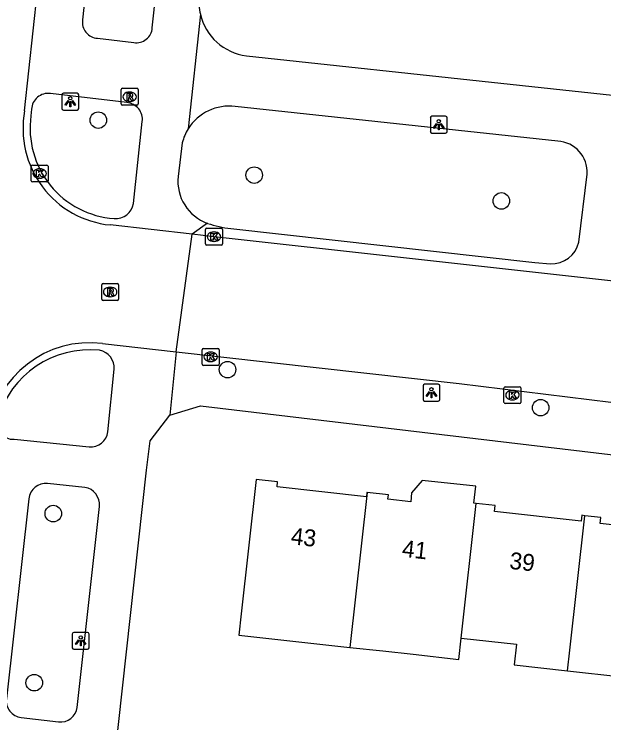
# Model space of a CAD drawing. Extents: x 162026 to 163499, y 387297 to 388169.
# Drawn here: x 162312.4 to 162347.33, y 387955.08 to 387997.02 of the extents above; entities that cross this region are included whole.
import ezdxf

# ---------------------------------------------------------------- set-up
doc = ezdxf.new("R2010")
doc.units = 0
for name, color, linetype in [('IMGEO_Boom', 7, 'Continuous'), ('IMGEO_Kolk', 7, 'Continuous'), ('IMGEO_Lichtpunt', 7, 'Continuous'), ('IMGEO_Pand', 7, 'Continuous'), ('IMGEO_Pand_nummerreeks', 7, 'Continuous'), ('IMGEO_Rijbaan_lokaal_gesloten', 7, 'Continuous'), ('IMGEO_Rijbaan_lokaal_open', 7, 'Continuous'), ('IMGEO_Rioolput', 7, 'Continuous'), ('IMGEO_Voetpad_open', 7, 'Continuous')]:
    doc.layers.add(name, color=color, linetype=linetype)

msp = doc.modelspace()

# ---------------------------------------------------------------- linework, layer by layer
at = {"layer": 'IMGEO_Boom'}
for centre in [(162317.382, 387990.753), (162326.617, 387987.499), (162341.256, 387985.971), (162325.039, 387975.985), (162343.583, 387973.734), (162314.714, 387967.468), (162313.588, 387957.457)]:
    msp.add_circle(centre, 0.489, dxfattribs=at)
at = {"layer": 'IMGEO_Kolk'}
for p, q in [((162313.403, 387987.169), (162313.403, 387988.021)), ((162313.478, 387988.095), (162314.33, 387988.095)), ((162314.404, 387988.021), (162314.404, 387987.169)), ((162313.891, 387987.875), (162313.916, 387987.875)), ((162314.33, 387987.095), (162313.478, 387987.095)), ((162313.914, 387987.315), (162313.889, 387987.315)), ((162323.732, 387983.428), (162323.732, 387984.28)), ((162323.807, 387984.354), (162324.659, 387984.354)), ((162324.733, 387984.28), (162324.733, 387983.428)), ((162324.22, 387984.134), (162324.245, 387984.134)), ((162324.659, 387983.354), (162323.807, 387983.354)), ((162324.243, 387983.574), (162324.218, 387983.574)), ((162323.534, 387976.315), (162323.534, 387977.167)), ((162323.609, 387977.241), (162324.461, 387977.241)), ((162324.022, 387977.021), (162324.047, 387977.021)), ((162324.535, 387977.167), (162324.535, 387976.315)), ((162324.461, 387976.241), (162323.609, 387976.241)), ((162324.045, 387976.461), (162324.02, 387976.461)), ((162341.487, 387974.975), (162342.339, 387974.975)), ((162341.412, 387974.049), (162341.412, 387974.901)), ((162341.9, 387974.755), (162341.925, 387974.755)), ((162342.413, 387974.901), (162342.413, 387974.049)), ((162341.923, 387974.195), (162341.898, 387974.195)), ((162342.339, 387973.975), (162341.487, 387973.975))]:
    msp.add_line(p, q, dxfattribs=at)
for points in [[(162313.403, 387987.169), (162313.403, 387988.021)], [(162313.478, 387988.095), (162314.33, 387988.095)], [(162314.404, 387988.021), (162314.404, 387987.169)], [(162313.724, 387987.795), (162313.847, 387987.795), (162313.847, 387987.644), (162313.977, 387987.795), (162314.141, 387987.795), (162313.995, 387987.644), (162314.148, 387987.395), (162313.996, 387987.395), (162313.911, 387987.559), (162313.847, 387987.492), (162313.847, 387987.395), (162313.724, 387987.395), (162313.724, 387987.795)], [(162314.33, 387987.095), (162313.478, 387987.095)], [(162323.732, 387983.428), (162323.732, 387984.28)], [(162323.807, 387984.354), (162324.659, 387984.354)], [(162324.733, 387984.28), (162324.733, 387983.428)], [(162324.053, 387984.054), (162324.176, 387984.054), (162324.176, 387983.903), (162324.306, 387984.054), (162324.47, 387984.054), (162324.324, 387983.903), (162324.477, 387983.654), (162324.325, 387983.654), (162324.24, 387983.818), (162324.176, 387983.751), (162324.176, 387983.654), (162324.053, 387983.654), (162324.053, 387984.054)], [(162324.659, 387983.354), (162323.807, 387983.354)], [(162323.534, 387976.315), (162323.534, 387977.167)], [(162323.609, 387977.241), (162324.461, 387977.241)], [(162324.535, 387977.167), (162324.535, 387976.315)], [(162323.855, 387976.941), (162323.978, 387976.941), (162323.978, 387976.79), (162324.108, 387976.941), (162324.272, 387976.941), (162324.126, 387976.79), (162324.279, 387976.541), (162324.127, 387976.541), (162324.042, 387976.705), (162323.978, 387976.638), (162323.978, 387976.541), (162323.855, 387976.541), (162323.855, 387976.941)], [(162324.461, 387976.241), (162323.609, 387976.241)], [(162341.487, 387974.975), (162342.339, 387974.975)], [(162341.412, 387974.049), (162341.412, 387974.901)], [(162341.733, 387974.675), (162341.856, 387974.675), (162341.856, 387974.524), (162341.986, 387974.675), (162342.15, 387974.675), (162342.004, 387974.524), (162342.157, 387974.275), (162342.005, 387974.275), (162341.92, 387974.439), (162341.856, 387974.372), (162341.856, 387974.275), (162341.733, 387974.275), (162341.733, 387974.675)], [(162342.413, 387974.901), (162342.413, 387974.049)], [(162342.339, 387973.975), (162341.487, 387973.975)]]:
    msp.add_lwpolyline(points, dxfattribs=at)
for centre, start, end in [((162313.48, 387988.019), 91.552, 178.448), ((162313.48, 387988.019), 91.552, 178.448), ((162314.328, 387988.019), 1.552, 88.448), ((162314.328, 387988.019), 1.552, 88.448), ((162313.48, 387987.171), 181.552, 268.448), ((162313.48, 387987.171), 181.552, 268.448), ((162314.328, 387987.171), 271.552, 358.448), ((162314.328, 387987.171), 271.552, 358.448), ((162323.809, 387984.278), 91.552, 178.448), ((162323.809, 387984.278), 91.552, 178.448), ((162324.657, 387984.278), 1.552, 88.448), ((162324.657, 387984.278), 1.552, 88.448), ((162323.809, 387983.43), 181.552, 268.448), ((162323.809, 387983.43), 181.552, 268.448), ((162324.657, 387983.43), 271.552, 358.448), ((162324.657, 387983.43), 271.552, 358.448), ((162323.611, 387977.165), 91.552, 178.448), ((162323.611, 387977.165), 91.552, 178.448), ((162324.459, 387977.165), 1.552, 88.448), ((162324.459, 387977.165), 1.552, 88.448), ((162323.611, 387976.317), 181.552, 268.448), ((162323.611, 387976.317), 181.552, 268.448), ((162324.459, 387976.317), 271.552, 358.448), ((162324.459, 387976.317), 271.552, 358.448), ((162341.489, 387974.899), 91.552, 178.448), ((162341.489, 387974.899), 91.552, 178.448), ((162342.337, 387974.899), 1.552, 88.448), ((162342.337, 387974.899), 1.552, 88.448), ((162341.489, 387974.051), 181.552, 268.448), ((162341.489, 387974.051), 181.552, 268.448), ((162342.337, 387974.051), 271.552, 358.448), ((162342.337, 387974.051), 271.552, 358.448)]:
    msp.add_arc(centre, 0.0765, start, end, dxfattribs=at)
for centre, major_axis, ratio, start_param, end_param in [((162313.89, 387987.595), (-0.387, 0.002), 0.722429, 4.712389, 7.853982), ((162313.915, 387987.595), (-0.39, 0.002), 0.717154, 1.570796, 4.712389), ((162324.219, 387983.854), (-0.387, 0.002), 0.722429, 4.712389, 7.853982), ((162324.244, 387983.854), (-0.39, 0.002), 0.717154, 1.570796, 4.712389), ((162324.021, 387976.741), (-0.387, 0.002), 0.722429, 4.712389, 7.853982), ((162324.046, 387976.741), (-0.39, 0.002), 0.717154, 1.570796, 4.712389), ((162341.899, 387974.475), (-0.387, 0.002), 0.722429, 4.712389, 7.853982), ((162341.924, 387974.475), (-0.39, 0.002), 0.717154, 1.570796, 4.712389)]:
    msp.add_ellipse(centre, major_axis=major_axis, ratio=ratio, start_param=start_param, end_param=end_param, dxfattribs=at)
at = {"layer": 'IMGEO_Lichtpunt'}
for p, q in [((162315.223, 387992.248), (162315.223, 387991.441)), ((162315.223, 387992.248), (162315.223, 387991.441)), ((162316.125, 387992.343), (162315.317, 387992.343)), ((162316.125, 387992.343), (162315.317, 387992.343)), ((162316.219, 387991.441), (162316.219, 387992.248)), ((162316.219, 387991.441), (162316.219, 387992.248)), ((162315.317, 387991.347), (162316.125, 387991.347)), ((162315.317, 387991.347), (162316.125, 387991.347)), ((162337.049, 387990.888), (162337.049, 387990.081)), ((162337.049, 387990.888), (162337.049, 387990.081)), ((162337.951, 387990.983), (162337.143, 387990.983)), ((162337.951, 387990.983), (162337.143, 387990.983)), ((162338.045, 387990.081), (162338.045, 387990.888)), ((162338.045, 387990.081), (162338.045, 387990.888)), ((162337.143, 387989.987), (162337.951, 387989.987)), ((162337.143, 387989.987), (162337.951, 387989.987)), ((162336.616, 387975.026), (162336.616, 387974.219)), ((162336.616, 387975.026), (162336.616, 387974.219)), ((162337.518, 387975.121), (162336.71, 387975.121)), ((162337.518, 387975.121), (162336.71, 387975.121)), ((162337.612, 387974.219), (162337.612, 387975.026)), ((162337.612, 387974.219), (162337.612, 387975.026)), ((162336.71, 387974.125), (162337.518, 387974.125)), ((162336.71, 387974.125), (162337.518, 387974.125)), ((162315.842, 387960.339), (162315.842, 387959.532)), ((162315.842, 387960.339), (162315.842, 387959.532)), ((162316.744, 387960.434), (162315.936, 387960.434)), ((162316.744, 387960.434), (162315.936, 387960.434)), ((162316.838, 387959.532), (162316.838, 387960.339)), ((162316.838, 387959.532), (162316.838, 387960.339)), ((162315.936, 387959.438), (162316.744, 387959.438)), ((162315.936, 387959.438), (162316.744, 387959.438))]:
    msp.add_line(p, q, dxfattribs=at)
for points in [[(162315.597, 387991.912), (162315.636, 387991.884), (162315.448, 387991.622), (162315.41, 387991.649), (162315.597, 387991.912)], [(162315.699, 387991.864), (162315.746, 387991.864), (162315.746, 387991.542), (162315.699, 387991.542), (162315.699, 387991.864)], [(162315.809, 387991.884), (162315.847, 387991.911), (162316.034, 387991.649), (162315.995, 387991.621), (162315.809, 387991.884)], [(162337.423, 387990.552), (162337.462, 387990.524), (162337.274, 387990.262), (162337.236, 387990.289), (162337.423, 387990.552)], [(162337.525, 387990.504), (162337.572, 387990.504), (162337.572, 387990.182), (162337.525, 387990.182), (162337.525, 387990.504)], [(162337.635, 387990.524), (162337.673, 387990.551), (162337.86, 387990.289), (162337.821, 387990.261), (162337.635, 387990.524)], [(162336.99, 387974.69), (162337.029, 387974.662), (162336.841, 387974.4), (162336.803, 387974.427), (162336.99, 387974.69)], [(162337.092, 387974.642), (162337.139, 387974.642), (162337.139, 387974.32), (162337.092, 387974.32), (162337.092, 387974.642)], [(162337.202, 387974.662), (162337.24, 387974.689), (162337.427, 387974.427), (162337.388, 387974.399), (162337.202, 387974.662)], [(162316.216, 387960.003), (162316.255, 387959.975), (162316.067, 387959.713), (162316.029, 387959.74), (162316.216, 387960.003)], [(162316.318, 387959.955), (162316.365, 387959.955), (162316.365, 387959.633), (162316.318, 387959.633), (162316.318, 387959.955)], [(162316.428, 387959.975), (162316.466, 387960.002), (162316.653, 387959.74), (162316.614, 387959.712), (162316.428, 387959.975)]]:
    msp.add_lwpolyline(points, dxfattribs=at)
for centre in [(162315.722, 387992.046), (162337.548, 387990.686), (162337.115, 387974.824), (162316.341, 387960.137)]:
    msp.add_circle(centre, 0.0994, dxfattribs=at)
for centre, start, end in [((162315.317, 387992.248), 90, 180), ((162315.317, 387992.248), 90, 180), ((162316.125, 387992.248), 0, 90), ((162316.125, 387992.248), 0, 90), ((162315.317, 387991.441), 180, 270), ((162315.317, 387991.441), 180, 270), ((162316.125, 387991.441), 270, 0), ((162316.125, 387991.441), 270, 360), ((162337.143, 387990.888), 90, 180), ((162337.143, 387990.888), 90, 180), ((162337.951, 387990.888), 0, 90), ((162337.951, 387990.888), 0, 90), ((162337.143, 387990.081), 180, 270), ((162337.143, 387990.081), 180, 270), ((162337.951, 387990.081), 270, 0), ((162337.951, 387990.081), 270, 360), ((162336.71, 387975.026), 90, 180), ((162336.71, 387975.026), 90, 180), ((162337.518, 387975.026), 0, 90), ((162337.518, 387975.026), 0, 90), ((162336.71, 387974.219), 180, 270), ((162336.71, 387974.219), 180, 270), ((162337.518, 387974.219), 270, 0), ((162337.518, 387974.219), 270, 360), ((162315.936, 387960.339), 90, 180), ((162315.936, 387960.339), 90, 180), ((162316.744, 387960.339), 0, 90), ((162316.744, 387960.339), 0, 90), ((162315.936, 387959.532), 180, 270), ((162315.936, 387959.532), 180, 270), ((162316.744, 387959.532), 270, 0), ((162316.744, 387959.532), 270, 360)]:
    msp.add_arc(centre, 0.0946, start, end, dxfattribs=at)
at = {"layer": 'IMGEO_Pand'}
for points in [[(162333.313, 387968.717), (162333.294, 387968.719), (162333.265, 387968.462), (162327.969, 387969.048), (162328.001, 387969.339), (162326.732, 387969.479), (162325.851, 387961.528), (162325.712, 387960.277), (162329.263, 387959.884), (162332.289, 387959.55)], [(162339.759, 387968.066), (162339.628, 387968.081), (162339.739, 387969.081), (162336.558, 387969.434), (162335.943, 387968.697), (162335.884, 387968.17), (162334.536, 387968.319), (162334.565, 387968.578), (162333.313, 387968.717)], [(162333.313, 387968.717), (162332.289, 387959.55)], [(162338.869, 387960.093), (162339.759, 387968.066)], [(162346.196, 387967.344), (162346.014, 387967.364), (162345.976, 387967.022), (162340.844, 387967.591), (162340.883, 387967.942), (162339.759, 387968.066)], [(162345.17, 387958.161), (162345.306, 387959.379), (162346.196, 387967.344)], [(162352.627, 387966.56), (162352.338, 387966.592), (162352.306, 387966.305), (162347.102, 387966.881), (162347.141, 387967.239), (162346.196, 387967.344)], [(162332.289, 387959.55), (162334.233, 387959.336), (162336.023, 387959.139), (162338.731, 387958.841), (162338.869, 387960.093)], [(162338.869, 387960.093), (162342.143, 387959.73), (162342.006, 387958.512), (162345.17, 387958.161)], [(162345.17, 387958.161), (162348.391, 387957.804), (162348.82, 387957.756), (162351.61, 387957.447), (162351.746, 387958.665)]]:
    msp.add_lwpolyline(points, dxfattribs=at)
at = {"layer": 'IMGEO_Rijbaan_lokaal_gesloten'}
for points in [[(162313.017, 387991.301), (162313.781, 387998.425)], [(162322.935, 387983.998), (162318.092, 387984.547)], [(162321.996, 387977.038), (162322.935, 387983.998)], [(162317.636, 387977.527), (162321.996, 387977.038)]]:
    msp.add_lwpolyline(points, dxfattribs=at)
for centre, radius, start, end in [((162318.653, 387990.252), 5.732, 169.4544, 264.3885), ((162316.878, 387971.502), 6.073, 82.8268, 172.2196)]:
    msp.add_arc(centre, radius, start, end, dxfattribs=at)
at = {"layer": 'IMGEO_Rijbaan_lokaal_open'}
for points in [[(162373.162, 387978.332), (162359.3, 387979.954), (162341.325, 387981.944), (162335.451, 387982.597), (162324.237, 387983.851), (162322.935, 387983.998)], [(162321.996, 387977.038), (162338.756, 387975.157), (162349.014, 387973.894), (162375.959, 387970.911), (162378.392, 387970.592), (162379.227, 387970.442)]]:
    msp.add_lwpolyline(points, dxfattribs=at)
at = {"layer": 'IMGEO_Rioolput'}
for p, q in [((162318.737, 387991.709), (162318.737, 387992.561)), ((162318.812, 387992.635), (162319.664, 387992.635)), ((162319.738, 387992.561), (162319.738, 387991.709)), ((162319.225, 387992.415), (162319.25, 387992.415)), ((162319.248, 387991.855), (162319.223, 387991.855)), ((162319.664, 387991.635), (162318.812, 387991.635)), ((162317.586, 387980.156), (162317.586, 387981.008)), ((162317.661, 387981.082), (162318.513, 387981.082)), ((162318.074, 387980.862), (162318.099, 387980.862)), ((162318.587, 387981.008), (162318.587, 387980.156)), ((162318.513, 387980.082), (162317.661, 387980.082)), ((162318.097, 387980.302), (162318.072, 387980.302))]:
    msp.add_line(p, q, dxfattribs=at)
for points in [[(162318.737, 387991.709), (162318.737, 387992.561)], [(162318.812, 387992.635), (162319.664, 387992.635)], [(162319.738, 387992.561), (162319.738, 387991.709)], [(162319.326, 387992.333), (162319.074, 387992.335), (162319.074, 387991.935)], [(162319.252, 387992.254), (162319.198, 387992.254), (162319.198, 387992.173)], [(162319.198, 387992.173), (162319.25, 387992.173)], [(162319.074, 387991.935), (162319.198, 387991.935), (162319.198, 387992.097), (162319.209, 387992.097)], [(162319.256, 387992.068), (162319.327, 387991.935), (162319.467, 387991.935), (162319.402, 387992.061)], [(162319.664, 387991.635), (162318.812, 387991.635)], [(162317.586, 387980.156), (162317.586, 387981.008)], [(162317.661, 387981.082), (162318.513, 387981.082)], [(162318.587, 387981.008), (162318.587, 387980.156)], [(162318.175, 387980.78), (162317.923, 387980.782), (162317.923, 387980.382)], [(162317.923, 387980.382), (162318.047, 387980.382), (162318.047, 387980.544), (162318.058, 387980.544)], [(162318.101, 387980.701), (162318.047, 387980.701), (162318.047, 387980.62)], [(162318.047, 387980.62), (162318.099, 387980.62)], [(162318.105, 387980.515), (162318.176, 387980.382), (162318.316, 387980.382), (162318.251, 387980.508)], [(162318.513, 387980.082), (162317.661, 387980.082)]]:
    msp.add_lwpolyline(points, dxfattribs=at)
for centre, radius, start, end in [((162318.814, 387992.559), 0.0765, 91.552, 178.448), ((162318.814, 387992.559), 0.0765, 91.552, 178.448), ((162319.662, 387992.559), 0.0765, 1.552, 88.448), ((162319.662, 387992.559), 0.0765, 1.552, 88.448), ((162319.234, 387992.362), 0.19, 274.7715, 282.9687), ((162319.258, 387992.158), 0.0964, 77.0061, 93.1865), ((162319.272, 387992.215), 0.0378, 276.6634, 79.6772), ((162319.325, 387992.223), 0.109, 350.3612, 89.416), ((162319.323, 387992.223), 0.112, 277.5842, 350.9817), ((162319.307, 387992.008), 0.108, 29.5134, 73.7905), ((162318.814, 387991.711), 0.0765, 181.552, 268.448), ((162318.814, 387991.711), 0.0765, 181.552, 268.448), ((162319.208, 387992.044), 0.0533, 26.0293, 88.6989), ((162319.662, 387991.711), 0.0765, 271.552, 358.448), ((162319.662, 387991.711), 0.0765, 271.552, 358.448), ((162317.663, 387981.006), 0.0765, 91.552, 178.448), ((162317.663, 387981.006), 0.0765, 91.552, 178.448), ((162318.511, 387981.006), 0.0765, 1.552, 88.448), ((162318.511, 387981.006), 0.0765, 1.552, 88.448), ((162318.057, 387980.491), 0.0533, 26.0293, 88.6989), ((162318.083, 387980.809), 0.19, 274.7715, 282.9687), ((162318.107, 387980.605), 0.0964, 77.0061, 93.1865), ((162318.121, 387980.662), 0.0378, 276.6634, 79.6772), ((162318.174, 387980.67), 0.109, 350.3612, 89.416), ((162318.172, 387980.67), 0.112, 277.5842, 350.9817), ((162318.156, 387980.455), 0.108, 29.5134, 73.7905), ((162317.663, 387980.158), 0.0765, 181.552, 268.448), ((162317.663, 387980.158), 0.0765, 181.552, 268.448), ((162318.511, 387980.158), 0.0765, 271.552, 358.448), ((162318.511, 387980.158), 0.0765, 271.552, 358.448)]:
    msp.add_arc(centre, radius, start, end, dxfattribs=at)
for centre, major_axis, ratio, start_param, end_param in [((162319.224, 387992.135), (-0.387, 0.002), 0.722429, 4.712389, 7.853982), ((162319.249, 387992.135), (-0.39, 0.002), 0.717154, 1.570796, 4.712389), ((162318.073, 387980.582), (-0.387, 0.002), 0.722429, 4.712389, 7.853982), ((162318.098, 387980.582), (-0.39, 0.002), 0.717154, 1.570796, 4.712389)]:
    msp.add_ellipse(centre, major_axis=major_axis, ratio=ratio, start_param=start_param, end_param=end_param, dxfattribs=at)
at = {"layer": 'IMGEO_Voetpad_open'}
for points in [[(162318.798, 388018.312), (162316.447, 387996.689)], [(162320.576, 387996.215), (162322.954, 388017.905)], [(162323.427, 387997.023), (162322.705, 387990.233)], [(162317.334, 387995.596), (162319.483, 387995.349)], [(162326.152, 387994.566), (162371.36, 387989.704), (162371.575, 387989.692)], [(162319.077, 387991.787), (162314.547, 387992.329)], [(162313.423, 387991.399), (162313.392, 387991.012)], [(162344.592, 387989.508), (162325.497, 387991.565)], [(162319.457, 387985.823), (162319.988, 387990.664)], [(162322.357, 387989.416), (162322.114, 387987.422)], [(162345.848, 387983.532), (162346.344, 387987.564)], [(162323.852, 387984.645), (162322.935, 387983.998)], [(162325.233, 387984.339), (162343.246, 387982.318), (162344.159, 387982.257)], [(162321.996, 387977.038), (162321.623, 387973.282)], [(162317.943, 387972.301), (162318.318, 387976.006)], [(162321.623, 387973.282), (162323.445, 387973.837), (162373.471, 387967.913)], [(162318.106, 387950.678), (162320.24, 387970.031), (162320.463, 387971.772), (162321.623, 387973.282)], [(162312.398, 387971.864), (162316.837, 387971.414)], [(162316.577, 387969.017), (162314.376, 387969.243)], [(162313.271, 387968.348), (162311.936, 387956.502)], [(162316.138, 387955.999), (162317.446, 387967.893)], [(162312.812, 387955.406), (162315.023, 387955.137)]]:
    msp.add_lwpolyline(points, dxfattribs=at)
for centre, radius, start, end in [((162326.553, 387997.742), 3.208, 174.359, 192.9455), ((162326.543, 387997.74), 3.198, 192.9494, 262.9717), ((162317.399, 387996.555), 0.962, 172.0182, 266.1024), ((162319.651, 387996.26), 0.926, 259.5627, 357.2179), ((162314.423, 387991.334), 1.002, 82.9029, 176.306), ((162318.999, 387990.793), 0.997, 352.5898, 85.5095), ((162325.144, 387988.713), 2.874, 82.9433, 148.0662), ((162318.687, 387990.263), 5.347, 171.9466, 266.0679), ((162325.126, 387988.719), 2.856, 147.9833, 165.8737), ((162344.495, 387987.659), 1.851, 357.0534, 86.9991), ((162324.733, 387987.128), 2.635, 173.6035, 250.4777), ((162318.424, 387985.966), 1.043, 264.301, 352.1157), ((162325.989, 387991.018), 6.722, 251.4666, 263.5461), ((162344.233, 387983.916), 1.66, 267.4578, 346.6393), ((162316.871, 387971.493), 5.666, 84.1002, 163.8486), ((162317.272, 387976.095), 1.05, 355.1486, 80.0625), ((162312.342, 387972.812), 0.95, 164.3094, 273.3573), ((162316.937, 387972.422), 1.013, 264.3139, 353.1445), ((162314.282, 387968.23), 1.018, 84.6796, 173.3322), ((162316.424, 387968.001), 1.028, 353.9852, 81.4323), ((162312.922, 387956.392), 0.992, 173.6196, 263.649), ((162315.128, 387956.153), 1.022, 264.096, 351.3188)]:
    msp.add_arc(centre, radius, start, end, dxfattribs=at)

# ---------------------------------------------------------------- texts
at = {"layer": 'IMGEO_Pand_nummerreeks'}
for s, rotation, p in [('43', 353.5886, (162328.75, 387965.66)), ('41', 353.5879, (162335.337, 387964.919)), ('39', 353.5886, (162341.7, 387964.205))]:
    msp.add_text(s, height=1, rotation=rotation, dxfattribs=at).set_placement(p)

doc.saveas('drawing.dxf')
